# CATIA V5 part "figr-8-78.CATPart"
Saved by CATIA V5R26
Part number: Part1
Bounding box of the stored display mesh (mm): x -35 to 35, y -116.369 to 116.369, z 0 to 117.647
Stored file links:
  D:\_Deepak\CATIA\CATIA V5-6R2016_Deepak\Resources\Part files\Partfiles\c08_catia_v5_6r2016_prt\figr-8-78.CATPart
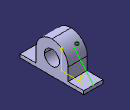
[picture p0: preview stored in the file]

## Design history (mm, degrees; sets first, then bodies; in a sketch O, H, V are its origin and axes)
Body1 (main body)
  Sketch1 on yz-plane, origin (0, 0, 0), H (0, 1, 0), V (0, 0, 1)
    line L1 (0, 0) -> (116.3687, 0)
    point P1 (116.3687, 0)
    line L2 (116.3687, 0) -> (116.3687, 12.5279)
    point P2 (116.3687, 12.5279)
    line L3 (116.3687, 12.5279) -> (58.943, 12.5279)
    point P3 (58.943, 12.5279)
    line L4 (58.943, 12.5279) -> (58.943, 58.7038)
    point P4 (58.943, 58.7038)
    arc A1 centre (0, 58.7038) radius 58.943 from (58.943, 58.7038) to (0, 117.6467) ccw
    point P5 (0, 58.7038)
    point P6 (-58.943, 58.7038)
    line L5 (-58.943, 58.7038) -> (-58.943, 12.5279)
    point P7 (-58.943, 12.5279)
    axis line L6 (0, 0) -> (0, 108.1111)
    point P9 (0, 117.6467)
    point P10 (0, 117.6467)
    point P11 (-58.943, 58.7038)
    arc A2 centre (0, 58.7038) radius 58.943 from (-58.943, 58.7038) to (0, 117.6467) cw
    point P13 (-58.943, 12.5279)
    point P14 (-116.3687, 12.5279)
    line L7 (-116.3687, 12.5279) -> (-58.943, 12.5279)
    point P15 (-116.3687, 0)
    line L8 (-116.3687, 0) -> (-116.3687, 12.5279)
    point P16 (0, 0)
    line L9 (0, 0) -> (-116.3687, 0)
    circle A3 centre (0, 58.7038) radius 27.1825
    horizontal: L1 H, L3 H
    vertical: L2 V, L4 V, L6 V
    tangency: A1 L4, L5 A1
    coincidence: P7 L3, P5 V, L6 P9, P6 P11, O P16, P9 P10, P7 P13
    symmetry: P9 P10 L6, P4 P11 L6, A1 A2 L6, P3 P13 L6, P2 P14 L6, L3 L7 L6, P1 P15 L6, L2 L8 L6, O P16 L6, L1 L9 L6
  Pad1: profile Sketch1, direction (1, 0, 0), length 35, mirrored extent
  Sketch2 on yz-plane, origin (0, 0, 0), H (0, 1, 0), V (0, 0, 1)
    line L1 (116.3687, 12.5279) -> (44.9741, 96.8037)
    point P1 (116.3687, 12.5279)
    point P2 (44.9741, 96.8037)
    reference projected arc E1 centre (0, 58.7038) radius 58.943 from (58.943, 58.7038) to (0, 117.6467) ccw from edge [face of Pad1 | face of Pad1]
    reference projected arc E2 centre (0, 58.7038) radius 58.943 from (58.943, 58.7038) to (0, 117.6467) ccw from edge [face of Pad1 | face of Pad1]
    reference projected point E3 (116.3687, 12.5279) from vertex [face of Pad1 | face of Pad1 | face of Pad1]
    tangency: L1 E1
    coincidence: P2 E2, P1 E3
  Stiffener1: ExtendedProfile Sketch2, ThicknessTop 0, ThicknessValue 15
